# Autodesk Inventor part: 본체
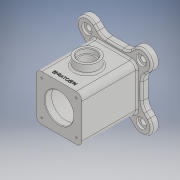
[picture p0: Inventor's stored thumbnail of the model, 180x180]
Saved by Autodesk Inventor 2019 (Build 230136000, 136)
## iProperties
Created: 2021-01
Part Number: 본체
Material: 일반
Document SubType Name: Modeling
Designer: 3dpro12
Density: 1 g/cm^3
Appearance: 기본값
Mass: 385.865 g
Surface Area: 854.376 cm^2
Volume: 385.865 cm^3
Author: 3dpro12
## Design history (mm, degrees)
sketch "스케치1"
  geometry: L1 (-40, -40)-(40, -40); L2 (40, -40)-(40, 40); L3 (40, 40)-(-40, 40); L4 (-40, 40)-(-40, -40); L5 (-40, -40)-(40, 40); L6 (40, -40)-(-40, 40); 1 further point
  constraints: 12 end point, 2 midpoint, 2 parallel, 1 horizontal, 1 perpendicular
  dimensions: "d0" = 80 distance of L3.end L2.end; "d1" = 80 distance of L2.end L1.end
extrude "돌출1" new body sketch "스케치1" stored distance "d2" = 108; taper "d3" = 0 deg
sketch "스케치2"
  geometry: L1 (-48, -48)-(48, -48); L2 (48, -48)-(48, 48); L3 (48, 48)-(-48, 48); L4 (-48, 48)-(-48, -48); L5 (-48, -48)-(48, 48); L6 (48, -48)-(-48, 48); 1 further point
  constraints: 12 end point, 2 midpoint, 2 parallel, 1 horizontal, 1 perpendicular
  dimensions: "d4" = 96 distance of L2.end L3.end; "d5" = 96 distance of L1.end L2.end
extrude "돌출2" join sketch "스케치2" distance "d6" = 12; taper "d7" = 0 deg
sketch "스케치4"
  geometry: L1 (0, 0)-(-47.376, 47.376); L2 (0, 0)-(67, 0); L3 (-60.104, 34.648)-(-48, 22.544); L4 (-48, -48)-(-48, 48) reference; L5 (-48, 48)-(48, 48) reference; L6 (-34.648, 60.104)-(-22.544, 48); A1 r 18 centre (-47.376, 47.376) between (-34.648, 60.104) and (-60.104, 34.648)
  constraints: 8 end point, 2 point on circle, 2 point on line, 1 centre point, 1 coincident, 1 equal length, 1 horizontal, 1 parallel
  dimensions: "d13" = 67 distance of L1.start L1.end; "d14" = 135 deg angle of L2 L1; "d16" = 18 radius of A1; "d17" = 36 distance between parallel lines of L3 L6
extrude "돌출3" join sketch "스케치4" distance "d18" = 12; taper "d19" = 0 deg
fillet "모깎기1" dims "d23" = 20
sketch "스케치5"
  geometry: L1 (-54, 0)-(54, 0); L2 (54, 0)-(54, 25); L3 (54, 25)-(42, 25); L4 (42, 25)-(42, 35); L5 (42, 35)-(-42, 35); L6 (-42, 35)-(-42, 25); L7 (-42, 25)-(-54, 25); L8 (-54, 25)-(-54, 0); 2 further points
  constraints: 16 end point, 6 perpendicular, 2 point on line, 1 coincident, 1 collinear, 1 horizontal, 1 midpoint
  dimensions: "d24" = 12 distance of L6.end L7.end; "d25" = 84 distance of L4.end L5.end; "d26" = 50 diameter of L7 L1; "d27" = 70 diameter of L5 L1
revolve "회전1" sketch "스케치5" stored, may be unused: angle "d28" = 90 deg
sketch "스케치6"
  geometry: L1 (108, 54.26)-(108, 25.74) reference; C1 r 20 at (49, 40); 1 further point
  constraints: 1 centre point, 1 horizontal alignment
  dimensions: "d29" = 40 diameter of C1; "d30" = 59 distance from line of C1.centre L1
extrude "돌출4" join sketch "스케치6" distance "d31" = 15; taper "d32" = 0 deg
sketch "스케치7"
  geometry: C1 r 20 at (0, 0) reference; 2 further points
  constraints: 1 coincident
hole "구멍1" sketch "스케치7" at (0, 0) diameter "d33" = 25; stored, may be unused: countersink angle "d37" = 90 deg, drill point angle "d39" = 0 deg; dims "d34" = 8, "d35" = 30, "d36" = 8, "d38" = 10
sketch "스케치8"
  geometry: A1 r 18 centre (-47.376, -47.376) between (-60.104, -34.648) and (-34.648, -60.104) reference; A2 r 18 centre (-47.376, 47.376) between (-34.648, 60.104) and (-60.104, 34.648) reference; A3 r 18 centre (47.376, 47.376) between (60.104, 34.648) and (34.648, 60.104) reference; A4 r 18 centre (47.376, -47.376) between (34.648, -60.104) and (60.104, -34.648) reference; 5 further points
  constraints: 4 coincident
hole "구멍2" sketch "스케치8" at (-47.376, -47.376), (-47.376, 47.376), (47.376, 47.376), (47.376, -47.376) diameter "d40" = 10; stored, may be unused: countersink angle "d44" = 90 deg, drill point angle "d46" = 0 deg; dims "d41" = 8, "d42" = 18, "d43" = 4, "d45" = 10
fillet "모깎기2" dims "d47" = 10
sketch "스케치9"
  geometry: A1 r 10 centre (-30, -30) between (-40, -30) and (-30, -40) reference; A2 r 10 centre (-30, 30) between (-30, 40) and (-40, 30) reference; A3 r 10 centre (30, 30) between (40, 30) and (30, 40) reference; A4 r 10 centre (30, -30) between (30, -40) and (40, -30) reference; 5 further points
  constraints: 4 coincident
hole "구멍3" sketch "스케치9" at (-30, -30), (-30, 30), (30, 30), (30, -30) diameter "d48" = 3.242; stored, may be unused: countersink angle "d52" = 90 deg, drill point angle "d54" = 118 deg; dims "d49" = 8, "d50" = 18, "d51" = 4, "d53" = 10
sketch "스케치10"
  geometry: L1 (0, -60)-(0, 0) reference; 2 further points
  constraints: 1 horizontal alignment, 1 other
  dimensions: "d55" = 10 distance from line of point (10, -30) L1
feature "엠보싱1" sketch "스케치10" dims "d0" = 80, "d1" = 80, "d56" = 0.5, "d57" = 0
fillet "모깎기3" dims "d58" = 3
chamfer "모따기1" distance "d59" = 1; stored, may be unused: second distance "d60" = 2, angle "d61" = 45 deg
node "솔리드1"
pattern_circular "원형 패턴1" dims angle "d21" = 360 deg
mirror "미러1"
other parameters: "d15" = 36
